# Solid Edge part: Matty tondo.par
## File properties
Title: Matty tondo
Author: DESYS
Template: Normal.par
Last saved by: i.fialdini
Revision: 16
Application: Solid Edge
Tipo di contenuto documento: 0
Precisione: 0,990
Document Number: 8055
Revision: 0
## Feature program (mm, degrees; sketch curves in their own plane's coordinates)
sketch for "unnamed RevolvedProtrusion 1" plane through (0, 0, 0) normal (0, -1, 0) x-axis (1, 0, 0)
  line (-103.4736, -287.9981) -> (-146.9731, -287.9981)
  arc centre (-146.9731, -282.9981) radius 5 from (-151.4083, -285.3065) to (-146.9731, -287.9981) ccw
  arc centre (469.5217, 37.8744) radius 700 from (-229.7181, 5.2599) to (-151.4083, -285.3065) ccw
  arc centre (-224.7235, 5.4929) radius 5 from (-223.4856, 10.3372) to (-229.7181, 5.2599) ccw
  line (-223.4856, 10.3372) -> (-198.051, 3.8377)
  arc centre (-199.2889, -1.0066) radius 5 from (-194.3913, 0) to (-198.051, 3.8377) ccw
  arc centre (50.4896, 50.3322) radius 250 from (-194.3913, 0) to (-25, -187.9981) ccw
  line (0, -187.9981) -> (-25, -187.9981)
  line (-30, -227.9981) -> (0, -227.9981)
  arc centre (-30, -222.9981) radius 5 from (-35, -222.9981) to (-30, -227.9981) ccw
  line (-35, -211.5908) -> (-35, -222.9981)
  arc centre (-40, -211.5908) radius 5 from (-35, -211.5908) to (-38.2474, -206.908) ccw
  arc centre (-20.7216, -160.0802) radius 50 from (-57.3248, -194.142) to (-38.2474, -206.908) ccw
  arc centre (-60.9851, -197.5482) radius 5 from (-57.3248, -194.142) to (-65.6708, -195.8034) ccw
  line (-98.7879, -284.7428) -> (-65.6708, -195.8034)
  arc centre (-103.4736, -282.9981) radius 5 from (-103.4736, -287.9981) to (-98.7879, -284.7428) ccw
  dimension (linear) = 223.4856
revolve "unnamed RevolvedProtrusion 1" add full turn 360 deg about sketch line (0, -187.9981) -> (0, -227.9981)
sketch for "unnamed RevolvedCutout 1" plane through (0, 0, 0) normal (1, 0, 0) x-axis (0, 1, 0)
  line (-227.9568, -21.4867) -> (-200.6198, -21.4867)
  arc centre (93.1464, 39.3526) radius 300 from (-200.6198, -21.4867) to (-71.4913, -211.435) ccw
revolve "unnamed RevolvedCutout 1" cut finite
fillet "Rotondo_1" radius 5
sketch for "Foro_1" plane through (0, 0, -187.9981) normal (0, 0, 1) x-axis (0, -1, 0)
  hole centre (0, 0) bore radius 25
hole "Foro_1" diameter 50 through
fillet "Rotondo_4" radius 10
sketch for "Foro_3" plane through (0, 9.4953, -287.9981) normal (0, 0, -1) x-axis (-0.34202, 0.939693, 0)
  hole centre (31.4357, -114.1313) bore radius 7.5
hole "Foro_3" diameter 15 finite
sketch for "unnamed Hole 1" plane through (0, 9.4953, -287.9981) normal (0, 0, -1) x-axis (-0.34202, 0.939693, 0)
  hole centre (-49.281, 107.6361) bore radius 7.5
hole "unnamed Hole 1" finite
sketch for "unnamed Hole 2" plane through (0, 9.4953, -287.9981) normal (0, 0, -1) x-axis (-0.34202, 0.939693, 0)
  hole centre (101.9611, 37.1108) bore radius 7.5
hole "unnamed Hole 2" finite
pattern "unnamed Pattern 1" of "Foro_3", "unnamed Hole 1", "unnamed Hole 2"
fillet "Rotondo_7" radius 5
sketch for "Foro_7" plane through (0, 0, 0) normal (0, -1, 0) x-axis (1, 0, 0)
hole "Foro_7" diameter 20 finite
sketch for "ScavoEstrusione_2" plane through (0, 0, 0) normal (1, 0, 0) x-axis (0, 1, 0)
  line (-227.9568, -21.4867) -> (-200.6198, -21.4867)
  arc centre (93.1464, 39.3526) radius 300 from (-200.6198, -21.4867) to (-71.4913, -211.435) ccw
extrude "ScavoEstrusione_2" cut finite 133 symmetric
draft "Spoglia_4"  Angles1 = 6.2 deg
draft "Spoglia_5"  Angles1 = 6.2 deg
fillet "Rotondo_8" radius 5
sketch for "ExtrudedProtrusion_2" plane through (0, 0, 0) normal (1, 0, 0) x-axis (0, 1, 0)
  arc centre (87.7883, 46.5058) radius 315.3865 from (-85.5645, -216.9662) to (-222.3824, -10.615) cw
  line (-198.5424, -10.615) -> (-222.3824, -10.615)
  line (-174.7282, -72.7389) -> (-198.5424, -10.615)
  line (-129.1706, -140.3849) -> (-174.7282, -72.7389)
  line (-26.903, -195.8034) -> (-129.1706, -140.3849)
  line (-26.903, -195.8034) -> (-26.903, -223.5492)
  line (-26.903, -223.5492) -> (-75.9297, -220.2121)
  arc centre (-74.5715, -200.2583) radius 20 from (-85.5645, -216.9662) to (-75.9297, -220.2121) ccw
extrude "ExtrudedProtrusion_2" add finite 30 symmetric
fillet "Rotondo_5" radius 5
fillet "Rotondo_9" radius 5
fillet "Rotondo_10" radius 5
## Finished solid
Body 1: solid body, 66 faces, 139 edges, 74 vertices.
  Faces by surface: cylinder 16, torus 16, plane 15, blend 13, sphere 4, cone 2
  Edges by curve: circle 60, intersection 50, line 24, ellipse 5
Bounding box of the edges (mm; curved faces can reach further): 459.436 x 459.436 x 298.335, from (-229.7181, -229.7181, -287.9981) to (229.7181, 229.7181, 10.3372).
Cylindrical faces by radius (mm): R5 x6, R7.5 x3, R10 x1, R20 x1, R25 x1, R35 x1, R300 x2, R315.3865 x1
Conical faces (half-angle, radius in mm at the cone's reference point): 20.4231 deg R65.6708 x1, 75.6654 deg R223.4856 x1
Toroidal faces (ring radius, tube radius in mm): R-469.5217 r700 x1, R-50.4896 r250 x1, R15 r5 x2, R20.7216 r50 x1, R30 r5 x1, R35 r10 x1, R40 r5 x1, R60.9851 r5 x1, R103.4736 r5 x1, R146.9731 r5 x1, R199.2889 r5 x1, R223.349 r5 x1, R224.7235 r5 x1, R310.3865 r5 x2
Spherical faces by radius (mm): R5 x4
Planar faces by outward normal: +x 1, -x 1, -z 7, oblique 6
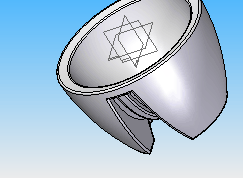
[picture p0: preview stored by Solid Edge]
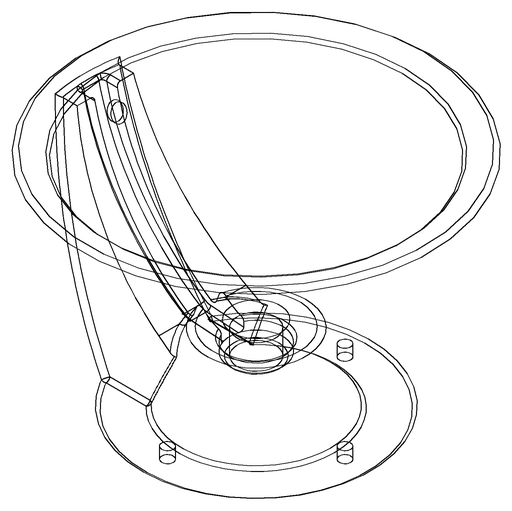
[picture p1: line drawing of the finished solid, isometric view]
